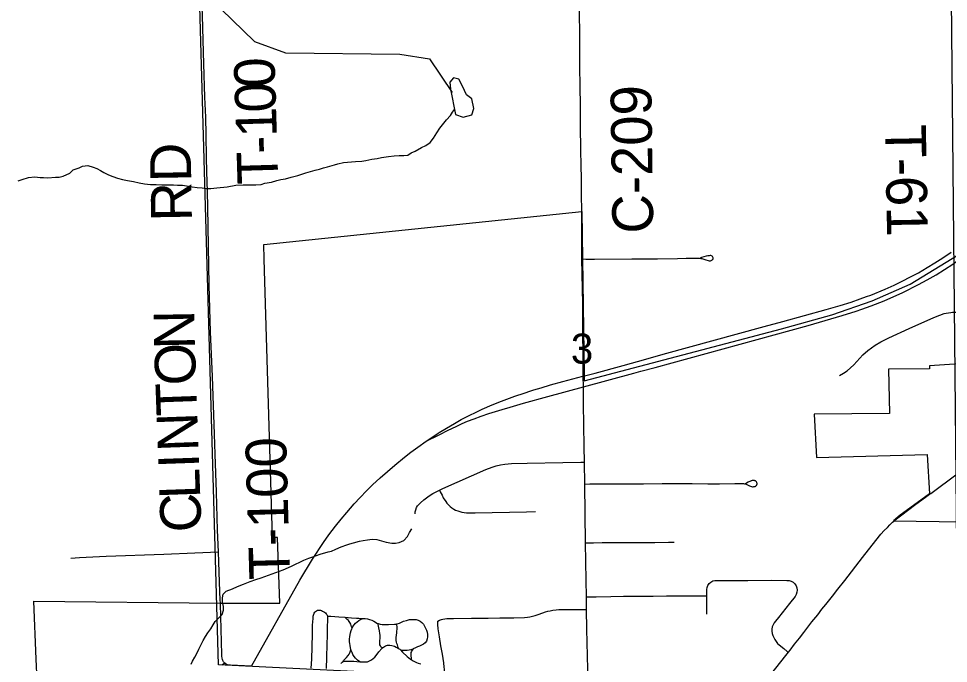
# Model space of a CAD drawing. Extents: x 0 to 34, y -5 to 22.
# Drawn here: x 2.826 to 4.121, y 15.62 to 16.518 of the extents above; entities that cross this region are included whole.
import ezdxf

# ---------------------------------------------------------------- set-up
doc = ezdxf.new("R2010")
doc.units = 0
for name, color, linetype in [('GM_X_City_Street', 7, 'Continuous'), ('GM_X_Corporation', 7, 'Continuous'), ('GM_X_County_Road', 7, 'Continuous'), ('GM_X_County_Road_Text', 7, 'Continuous'), ('GM_X_Minor_Lake', 7, 'Continuous'), ('GM_X_Minor_River', 7, 'Continuous'), ('GM_X_Rail_Line', 7, 'Continuous'), ('GM_X_Section', 7, 'Continuous'), ('GM_X_Section_Text', 7, 'Continuous'), ('GM_X_State_Route', 7, 'Continuous'), ('GM_X_Township_Road', 7, 'Continuous'), ('GM_X_Township_Road_Text', 7, 'Continuous')]:
    doc.layers.add(name, color=color, linetype=linetype)

msp = doc.modelspace()

# ---------------------------------------------------------------- linework, layer by layer
at = {"layer": 'GM_X_City_Street'}
for points in [[(3.9694, 16.021), (3.9748, 16.024), (3.98, 16.0275), (3.9848, 16.0315), (3.9892, 16.0358), (4.002, 16.0495), (4.0089, 16.0558), (4.0138, 16.0596), (4.0189, 16.0632), (4.027, 16.0678), (4.0382, 16.0733), (4.0666, 16.0862), (4.1006, 16.1016), (4.1092, 16.1052), (4.1151, 16.1072), (4.1181, 16.1079), (4.1243, 16.1088), (4.1266, 16.109), (4.1323, 16.1092), (4.1342, 16.1093)], [(3.3782, 15.8279), (3.3785, 15.8309), (3.3792, 15.8338), (3.3802, 15.8367), (3.3816, 15.8392), (3.3835, 15.8413), (3.3858, 15.8434), (3.3906, 15.8474), (3.398, 15.853), (3.4031, 15.8563), (3.4085, 15.8593), (3.4121, 15.861), (3.4169, 15.8633), (3.4767, 15.8899), (3.4854, 15.8932), (3.4913, 15.895), (3.4973, 15.8963), (3.5034, 15.8973), (3.5126, 15.898), (3.5344, 15.8985), (3.5842, 15.8995), (3.6092, 15.9002), (3.6144, 15.9003)], [(3.4121, 15.861), (3.4132, 15.8587), (3.4157, 15.8539), (3.4175, 15.8506), (3.4208, 15.8453), (3.4226, 15.8428), (3.4247, 15.8405), (3.427, 15.8384), (3.4294, 15.8364), (3.432, 15.8347), (3.4347, 15.8333), (3.4376, 15.8321), (3.4405, 15.8311), (3.4435, 15.8303), (3.4466, 15.8297), (3.4497, 15.8295), (3.4621, 15.8296), (3.5335, 15.8309), (3.5459, 15.8313)], [(3.6157, 15.7875), (3.6189, 15.7876), (3.6267, 15.7878), (3.6386, 15.7879), (3.6504, 15.7879), (3.6785, 15.7881), (3.7123, 15.7883), (3.7312, 15.7885), (3.739, 15.7885)], [(3.7846, 15.6881), (3.7847, 15.7006), (3.7846, 15.7139), (3.7846, 15.7224), (3.7849, 15.7255), (3.7859, 15.7284), (3.7876, 15.731), (3.79, 15.733), (3.7928, 15.7345), (3.7958, 15.7351), (3.8051, 15.7353), (3.8301, 15.7352), (3.8419, 15.7352), (3.8741, 15.7354), (3.896, 15.7353), (3.8991, 15.7351), (3.9021, 15.7341), (3.9048, 15.7326), (3.9071, 15.7305), (3.9088, 15.7279), (3.91, 15.725), (3.9103, 15.7219), (3.9101, 15.7187), (3.9091, 15.7157), (3.9075, 15.713), (3.8997, 15.7032), (3.8843, 15.6835), (3.8804, 15.6786), (3.8785, 15.6761), (3.8769, 15.6734), (3.8757, 15.6705), (3.8751, 15.6675), (3.8751, 15.6643), (3.8756, 15.6613), (3.8767, 15.6583), (3.8795, 15.6527), (3.8811, 15.65), (3.8829, 15.6475), (3.8852, 15.6453), (3.8918, 15.6404), (3.8966, 15.6364), (3.8982, 15.6351)], [(3.6168, 15.7124), (3.6207, 15.7124), (3.6305, 15.7125), (3.6509, 15.713), (3.6686, 15.7131), (3.6879, 15.7133), (3.7096, 15.7135), (3.7283, 15.7138), (3.7533, 15.7137), (3.775, 15.7139), (3.7823, 15.7139), (3.7846, 15.7139)], [(3.2334, 15.6128), (3.2342, 15.6256), (3.2352, 15.6604), (3.2355, 15.6728), (3.236, 15.6821), (3.2364, 15.6852), (3.2372, 15.6882), (3.2377, 15.6896), (3.2386, 15.6909), (3.2396, 15.6921), (3.2407, 15.693), (3.2422, 15.6937), (3.2435, 15.6939), (3.245, 15.6939), (3.2464, 15.6937), (3.2478, 15.6932), (3.2493, 15.6924), (3.252, 15.6909), (3.2533, 15.6899), (3.2544, 15.6889), (3.2553, 15.6879), (3.2559, 15.6866), (3.2561, 15.6853), (3.2564, 15.684), (3.2564, 15.6821), (3.256, 15.6796), (3.2558, 15.6709), (3.2557, 15.6586), (3.2554, 15.6462), (3.2548, 15.6277), (3.2543, 15.6125)], [(3.2561, 15.6853), (3.2609, 15.6855), (3.2721, 15.6847), (3.2805, 15.684), (3.2898, 15.6832), (3.2966, 15.6827), (3.2997, 15.6825), (3.3033, 15.6824), (3.3058, 15.6822), (3.3087, 15.6821), (3.3121, 15.6816), (3.3149, 15.681), (3.3179, 15.6799), (3.3205, 15.6786), (3.3231, 15.677), (3.3251, 15.6757), (3.3267, 15.6752), (3.3296, 15.6743), (3.3325, 15.6739), (3.335, 15.6739), (3.3413, 15.674), (3.3495, 15.6744), (3.3517, 15.6745), (3.3529, 15.6748), (3.3548, 15.6752), (3.3565, 15.6758), (3.3592, 15.6771), (3.3622, 15.6783), (3.3662, 15.6796), (3.3703, 15.6807), (3.3734, 15.681), (3.3765, 15.681), (3.3796, 15.6806), (3.3825, 15.6797), (3.3852, 15.6783), (3.3877, 15.6764), (3.3897, 15.6741), (3.3915, 15.6715), (3.3929, 15.6688), (3.3941, 15.6659), (3.3949, 15.6629), (3.3955, 15.6599), (3.3956, 15.6568), (3.3951, 15.6537), (3.394, 15.6508), (3.3921, 15.6484), (3.3897, 15.6465), (3.387, 15.6449), (3.3842, 15.6436), (3.3817, 15.6425), (3.3786, 15.6411), (3.3757, 15.6397), (3.3738, 15.6376), (3.373, 15.6364), (3.3724, 15.6348), (3.3721, 15.6333), (3.3721, 15.6318), (3.3722, 15.63), (3.3726, 15.6271), (3.3728, 15.6249)], [(3.4097, 15.6784), (3.4124, 15.6798), (3.4148, 15.6808), (3.4169, 15.6814), (3.4194, 15.6819), (3.4225, 15.6822), (3.4316, 15.6823), (3.4567, 15.6827), (3.4799, 15.6828), (3.4964, 15.683), (3.5159, 15.6833), (3.5307, 15.6836), (3.5346, 15.684), (3.5381, 15.6845), (3.5419, 15.6853), (3.5453, 15.6862), (3.5511, 15.6882), (3.5599, 15.6914), (3.5632, 15.6923), (3.5662, 15.693), (3.5701, 15.6937), (3.5746, 15.6943), (3.5783, 15.6945), (3.5937, 15.6948), (3.6061, 15.6948), (3.6145, 15.6948), (3.617, 15.6947)], [(3.2906, 15.6686), (3.2898, 15.6707), (3.2886, 15.6743), (3.2875, 15.6764), (3.2866, 15.6778), (3.2853, 15.6794), (3.2833, 15.6814), (3.2813, 15.6832), (3.2805, 15.684)], [(3.301, 15.622), (3.2978, 15.6243), (3.2966, 15.6253), (3.2951, 15.6268), (3.2933, 15.6292), (3.2917, 15.632), (3.2904, 15.6348), (3.2893, 15.6376), (3.2889, 15.639), (3.2883, 15.6411), (3.2877, 15.6445), (3.2872, 15.6475), (3.287, 15.6498), (3.287, 15.6536), (3.2873, 15.6568), (3.2877, 15.6598), (3.2883, 15.6624), (3.2893, 15.6655), (3.2903, 15.668), (3.2906, 15.6686), (3.2917, 15.6708), (3.2934, 15.6734), (3.2952, 15.6756), (3.2974, 15.6777), (3.2998, 15.6794), (3.3013, 15.6803), (3.3028, 15.6811), (3.3046, 15.6817), (3.3058, 15.6822)], [(3.3327, 15.6411), (3.3318, 15.6419), (3.3311, 15.6424), (3.3306, 15.643), (3.3298, 15.6441), (3.3293, 15.6454), (3.3292, 15.647), (3.3292, 15.65), (3.3296, 15.6559), (3.3295, 15.6589), (3.3292, 15.6613), (3.3286, 15.6648), (3.3275, 15.6691), (3.3271, 15.6715), (3.3269, 15.6739), (3.3267, 15.6752)], [(3.3553, 15.6403), (3.3548, 15.6419), (3.3535, 15.6453), (3.3528, 15.6473), (3.3522, 15.6494), (3.352, 15.6517), (3.3519, 15.6539), (3.352, 15.6558), (3.3526, 15.6622), (3.3529, 15.665), (3.353, 15.667), (3.353, 15.67), (3.3529, 15.6737), (3.3529, 15.6748)], [(3.4191, 15.6022), (3.4191, 15.6043), (3.4191, 15.6081), (3.419, 15.6103), (3.419, 15.6115), (3.4187, 15.6143), (3.4181, 15.6203), (3.4162, 15.6325), (3.4142, 15.6442), (3.4121, 15.6568), (3.4104, 15.6677), (3.4099, 15.6736), (3.4097, 15.6784)], [(3.275, 15.6195), (3.2756, 15.6205), (3.2765, 15.6214), (3.2778, 15.6223), (3.2796, 15.6225), (3.2815, 15.6226), (3.2848, 15.6226), (3.2927, 15.6225), (3.2972, 15.6223), (3.301, 15.622), (3.3045, 15.6219), (3.3072, 15.6218), (3.3098, 15.6218), (3.3117, 15.622), (3.3146, 15.6231), (3.3173, 15.6246), (3.3198, 15.6264), (3.3221, 15.6285), (3.324, 15.6308), (3.3278, 15.6357), (3.3319, 15.6404), (3.3327, 15.6411), (3.3342, 15.6424), (3.3369, 15.6439), (3.3398, 15.6448), (3.3429, 15.6451), (3.346, 15.6447), (3.3493, 15.6436), (3.352, 15.6424), (3.3539, 15.6414), (3.3553, 15.6403), (3.3568, 15.6393), (3.3578, 15.6383), (3.3608, 15.6353), (3.3671, 15.6294), (3.3717, 15.6257), (3.3728, 15.6249), (3.3756, 15.6231), (3.3783, 15.6217), (3.3802, 15.6208), (3.3827, 15.62), (3.386, 15.6192)], [(3.2778, 15.6223), (3.2786, 15.6235), (3.2797, 15.6248), (3.2827, 15.6278), (3.2851, 15.6305), (3.2864, 15.6324), (3.2874, 15.6344), (3.2882, 15.6369), (3.2889, 15.639)], [(3.3578, 15.6383), (3.3592, 15.6382), (3.3618, 15.638), (3.3643, 15.638), (3.367, 15.6381), (3.37, 15.6384), (3.3728, 15.6389), (3.3757, 15.6397)]]:
    msp.add_lwpolyline(points, dxfattribs=at)
at = {"layer": 'GM_X_Corporation'}
for points in [[(2.8518, 15.5958), (2.8506, 15.6253), (2.8471, 15.7063), (3.1069, 15.7037), (3.1897, 15.7036), (3.1867, 15.7952), (3.1797, 15.7951), (3.1679, 16.1829), (3.1674, 16.2037), (3.6104, 16.2495), (3.6116, 16.1837), (3.6137, 16.021), (3.6138, 16.0135), (3.8888, 16.0861), (3.9589, 16.1056), (4.0147, 16.125), (4.0677, 16.1481), (4.1346, 16.189)], [(4.1366, 16.0371), (4.0945, 16.0344), (4.0945, 16.0303), (4.0377, 16.0297), (4.0388, 15.968), (3.9339, 15.9668), (3.9371, 15.9064), (4.0913, 15.9107), (4.0946, 15.856), (4.054, 15.8261), (4.0447, 15.8182), (4.1399, 15.8168)], [(3.1147, 15.6191), (3.1131, 15.6201), (3.1088, 15.6173)]]:
    msp.add_lwpolyline(points, dxfattribs=at)
at = {"layer": 'GM_X_County_Road'}
for p, q in [((3.6106, 16.1833), (3.6106, 16.2489)), ((3.6126, 16.005), (3.6125, 16.02)), ((3.6145, 15.8695), (3.6144, 15.9003)), ((4.0956, 15.856), (4.0964, 15.8566)), ((3.6164, 15.7354), (3.6157, 15.7875)), ((3.6168, 15.7124), (3.6164, 15.7354)), ((3.617, 15.6947), (3.6168, 15.7124))]:
    msp.add_line(p, q, dxfattribs=at)
for points in [[(3.6106, 16.2489), (3.6102, 16.2742), (3.6099, 16.2866), (3.6098, 16.2985), (3.6097, 16.3108), (3.6092, 16.3377), (3.6088, 16.366), (3.6084, 16.3982), (3.6081, 16.4228), (3.6078, 16.4524), (3.6077, 16.4706), (3.6075, 16.498), (3.6073, 16.5248), (3.6072, 16.543)], [(3.6125, 16.02), (3.6125, 16.0421), (3.6119, 16.088), (3.6118, 16.1207), (3.6106, 16.1833)], [(3.6144, 15.9003), (3.6137, 15.9218), (3.613, 15.9816), (3.6126, 16.005)], [(4.0964, 15.8566), (4.1332, 15.884), (4.1401, 15.8892)], [(3.6157, 15.7875), (3.6151, 15.8279), (3.6145, 15.8695)], [(4.0456, 15.8183), (4.0487, 15.821), (4.0542, 15.8255), (4.0759, 15.8417), (4.0892, 15.8513), (4.0948, 15.8555), (4.0956, 15.856)], [(3.8982, 15.6351), (3.9005, 15.638), (3.9069, 15.6463), (3.9138, 15.6549), (3.9197, 15.6627), (3.9254, 15.6699), (3.931, 15.6773), (3.9391, 15.6875), (3.9448, 15.695), (3.9502, 15.7015), (3.9595, 15.7133), (3.9671, 15.7229), (3.9767, 15.7351), (4.0015, 15.767), (4.0201, 15.7911), (4.0271, 15.7995), (4.0317, 15.8048), (4.036, 15.8092), (4.0396, 15.8128), (4.0434, 15.8164), (4.0449, 15.8177), (4.0456, 15.8183)], [(3.6193, 15.5928), (3.6173, 15.6675), (3.617, 15.6947)], [(3.868, 15.5971), (3.8748, 15.6056), (3.8805, 15.6129), (3.8948, 15.6308), (3.8982, 15.6351)]]:
    msp.add_lwpolyline(points, dxfattribs=at)
at = {"layer": 'GM_X_Minor_Lake'}
for points in [[(3.4343, 16.3849), (3.4453, 16.3811), (3.4571, 16.3843), (3.46, 16.393), (3.4573, 16.4067), (3.45, 16.4123), (3.4442, 16.4244), (3.4392, 16.4339), (3.4316, 16.4357), (3.4267, 16.43), (3.4276, 16.4201)], [(3.4276, 16.4201), (3.4343, 16.3849)]]:
    msp.add_lwpolyline(points, dxfattribs=at)
at = {"layer": 'GM_X_Minor_River'}
for points in [[(3.0872, 16.2816), (3.0936, 16.2814), (3.102, 16.2827), (3.1164, 16.2841), (3.1286, 16.2862), (3.1385, 16.2868), (3.1442, 16.2865), (3.1563, 16.2868), (3.1636, 16.2873), (3.1689, 16.2889), (3.1784, 16.2906), (3.1855, 16.2927), (3.1912, 16.2943), (3.1977, 16.2952), (3.2056, 16.2972), (3.2147, 16.2997), (3.2204, 16.3013), (3.2261, 16.3033), (3.2325, 16.3054), (3.2389, 16.307), (3.245, 16.3086), (3.2507, 16.3103), (3.256, 16.3119), (3.2658, 16.3144), (3.2707, 16.316), (3.2783, 16.318), (3.295, 16.3191), (3.3038, 16.3197), (3.3095, 16.3205), (3.3178, 16.3226), (3.3254, 16.3235), (3.3315, 16.3248), (3.3413, 16.3261), (3.3489, 16.327), (3.3562, 16.3275), (3.3626, 16.3276), (3.3683, 16.3281), (3.3728, 16.3313), (3.3785, 16.3337), (3.3872, 16.3388), (3.3932, 16.3415), (3.3992, 16.3459), (3.404, 16.3517), (3.4085, 16.3593), (3.4125, 16.3655), (3.4162, 16.3705), (3.4218, 16.3771), (3.4274, 16.3833), (3.4304, 16.3879), (3.433, 16.3915)], [(2.8251, 16.2922), (2.8311, 16.2942), (2.8398, 16.2971), (2.8486, 16.2976), (2.8558, 16.297), (2.8604, 16.2967), (2.8665, 16.2964), (2.8771, 16.2974), (2.8825, 16.2975), (2.8881, 16.2988), (2.8972, 16.3031), (2.9021, 16.3078), (2.9104, 16.3102), (2.9149, 16.3126), (2.9225, 16.3135), (2.9298, 16.3114), (2.9351, 16.3092), (2.9401, 16.3066), (2.9448, 16.3037), (2.9513, 16.3007), (2.9571, 16.2982), (2.9636, 16.296), (2.9705, 16.2939), (2.9777, 16.2925), (2.9861, 16.2911), (2.9938, 16.2894), (3.0014, 16.288), (3.0098, 16.287), (3.0174, 16.2872), (3.0254, 16.2865), (3.0368, 16.2868), (3.0418, 16.2865), (3.0471, 16.2862), (3.054, 16.286), (3.0628, 16.2846), (3.0677, 16.2839), (3.0746, 16.2829), (3.0814, 16.2823), (3.0872, 16.2816)], [(3.0661, 15.6183), (3.0683, 15.6229), (3.0713, 15.6283), (3.0746, 15.6344), (3.0772, 15.6394), (3.0793, 15.644), (3.083, 15.6513), (3.0863, 15.6571), (3.0897, 15.6621), (3.0937, 15.6679), (3.097, 15.6733), (3.0996, 15.6779), (3.1052, 15.6834), (3.1097, 15.6876), (3.1115, 15.6938), (3.1114, 15.6991), (3.1098, 15.7051), (3.11, 15.7112), (3.1107, 15.7162), (3.1152, 15.7201), (3.1239, 15.7233), (3.131, 15.7269), (3.1393, 15.7301), (3.1484, 15.7337), (3.1563, 15.7365), (3.1639, 15.7389), (3.1945, 15.7498), (3.2062, 15.7553), (3.2232, 15.7633), (3.23, 15.7661), (3.2357, 15.7681), (3.2459, 15.7717), (3.2572, 15.7749), (3.2618, 15.7762), (3.2678, 15.779), (3.275, 15.7821), (3.2829, 15.785), (3.2875, 15.7862), (3.2924, 15.7878), (3.3007, 15.7902), (3.3057, 15.7907), (3.3121, 15.792), (3.3182, 15.7929), (3.3247, 15.7922), (3.3315, 15.7905), (3.338, 15.7887), (3.3457, 15.7873), (3.351, 15.7874), (3.3559, 15.7883), (3.3624, 15.7907), (3.3676, 15.7965), (3.3705, 15.8022), (3.3735, 15.8072)]]:
    msp.add_lwpolyline(points, dxfattribs=at)
at = {"layer": 'GM_X_Rail_Line'}
msp.add_lwpolyline([(3.1083, 16.5313), (3.1544, 16.4864), (3.1977, 16.4708), (3.357, 16.469), (3.3985, 16.4621), (3.4297, 16.4153)], dxfattribs=at)
at = {"layer": 'GM_X_Section'}
msp.add_lwpolyline([(4.1248, 16.5469), (4.1342, 15.5936), (3.6228, 15.592), (3.1044, 15.6177), (3.0783, 16.5351), (3.1825, 16.5361), (3.5929, 16.5408), (3.9967, 16.5453)], close=True, dxfattribs=at)
at = {"layer": 'GM_X_State_Route'}
msp.add_line((3.6126, 16.005), (3.683, 16.0242), dxfattribs=at)
for points in [[(3.6125, 16.02), (3.6288, 16.0243), (3.6679, 16.0349), (3.6997, 16.0438), (3.7238, 16.0506), (3.8644, 16.089), (3.8906, 16.0962), (3.9508, 16.1129), (3.9701, 16.1185), (3.9854, 16.1232), (3.9983, 16.1276), (4.007, 16.1308), (4.0131, 16.1331), (4.0332, 16.1413), (4.0456, 16.147), (4.055, 16.1514), (4.0701, 16.1592), (4.0793, 16.1642), (4.0915, 16.1713), (4.1022, 16.1779), (4.1132, 16.1849), (4.1251, 16.1927)], [(3.683, 16.0242), (3.6927, 16.0268), (3.7126, 16.0321), (3.9256, 16.0904), (3.9572, 16.0997), (3.973, 16.1043), (3.9927, 16.1107), (4.0005, 16.1133), (4.0136, 16.118), (4.0318, 16.1251), (4.0574, 16.1364), (4.0795, 16.1476), (4.0915, 16.1542), (4.1038, 16.1614), (4.1274, 16.1763), (4.1348, 16.1815)], [(3.5435, 16.0007), (3.554, 16.0039), (3.5668, 16.0077), (3.584, 16.0123), (3.6118, 16.0198), (3.6125, 16.02)], [(3.3938, 15.9293), (3.4116, 15.9382), (3.4243, 15.9446), (3.4356, 15.95), (3.444, 15.9539), (3.4513, 15.9571), (3.4605, 15.9607), (3.4701, 15.9641), (3.4811, 15.9678), (3.4996, 15.9736), (3.5108, 15.9768), (3.529, 15.9821), (3.5631, 15.9915), (3.6126, 16.005)], [(3.3938, 15.9293), (3.4031, 15.9356), (3.409, 15.9397), (3.4117, 15.9413), (3.4221, 15.9475), (3.4332, 15.9541), (3.4423, 15.9594), (3.4533, 15.9653), (3.4631, 15.97), (3.4714, 15.9739), (3.4854, 15.9799), (3.4987, 15.9852), (3.5172, 15.9919), (3.5299, 15.9964), (3.5396, 15.9996), (3.5435, 16.0007)], [(3.1503, 15.6156), (3.2177, 15.7357), (3.2353, 15.7649), (3.2508, 15.7881), (3.258, 15.7986), (3.2672, 15.8107), (3.2754, 15.8208), (3.2829, 15.83), (3.2932, 15.8419), (3.3015, 15.8507), (3.3106, 15.86), (3.3189, 15.8684), (3.3294, 15.8782), (3.3396, 15.8872), (3.3498, 15.8961), (3.3635, 15.907), (3.3721, 15.9138), (3.3818, 15.9208), (3.3938, 15.9293)]]:
    msp.add_lwpolyline(points, dxfattribs=at)
at = {"layer": 'GM_X_Township_Road'}
for points in [[(3.1042, 15.7751), (3.1029, 15.8055), (3.1014, 15.8584), (3.0997, 15.9112), (3.0987, 15.9391), (3.0958, 16.0196), (3.0932, 16.0816), (3.0915, 16.1469), (3.0896, 16.2555), (3.089, 16.2772), (3.0883, 16.3048), (3.0878, 16.3248), (3.0873, 16.3562), (3.0865, 16.381), (3.0854, 16.4089), (3.0839, 16.4553), (3.0826, 16.5049), (3.082, 16.5233), (3.0817, 16.534), (3.0817, 16.5373)], [(3.6106, 16.1833), (3.6161, 16.1831), (3.6282, 16.1831), (3.6803, 16.1833), (3.7157, 16.1837), (3.7436, 16.184), (3.756, 16.1846), (3.7684, 16.1846), (3.7745, 16.1844), (3.776, 16.1842), (3.7775, 16.1839), (3.7805, 16.183), (3.7834, 16.182), (3.7864, 16.1811), (3.788, 16.1808), (3.7895, 16.1808), (3.7907, 16.1812), (3.7917, 16.1816), (3.7922, 16.182), (3.7927, 16.1825), (3.7934, 16.1839), (3.7934, 16.1847), (3.7929, 16.1859), (3.7925, 16.1866), (3.792, 16.1871), (3.791, 16.1877), (3.79, 16.188), (3.789, 16.188), (3.788, 16.1879), (3.7859, 16.1876), (3.7836, 16.187), (3.7773, 16.1852), (3.7753, 16.1846)], [(3.6145, 15.8695), (3.6215, 15.87), (3.6494, 15.8699), (3.6742, 15.8699), (3.6964, 15.87), (3.7222, 15.8702), (3.7426, 15.8702), (3.7642, 15.8704), (3.786, 15.8701), (3.802, 15.87), (3.8235, 15.8703), (3.8325, 15.8704), (3.8358, 15.8703), (3.8369, 15.8701), (3.8378, 15.8699), (3.8394, 15.8692), (3.8439, 15.8672), (3.847, 15.866), (3.8481, 15.8658), (3.8492, 15.8659), (3.8502, 15.866), (3.851, 15.8661), (3.8519, 15.8664), (3.8527, 15.8668), (3.8535, 15.8674), (3.854, 15.868), (3.8543, 15.8688), (3.8545, 15.8696), (3.8545, 15.8703), (3.8544, 15.8711), (3.8541, 15.8719), (3.8538, 15.8725), (3.8534, 15.8731), (3.8528, 15.8735), (3.8523, 15.8739), (3.8516, 15.8742), (3.8508, 15.8744), (3.8499, 15.8745), (3.8484, 15.8745), (3.8477, 15.8744), (3.8469, 15.8742), (3.8462, 15.8739), (3.8453, 15.8736), (3.8422, 15.8721), (3.8397, 15.8709), (3.8381, 15.87)], [(2.8986, 15.7665), (2.9109, 15.7674), (2.948, 15.769), (3.0283, 15.7719), (3.0716, 15.7735), (3.1042, 15.7751)], [(3.1069, 15.7076), (3.1059, 15.7326), (3.1048, 15.761), (3.1042, 15.7751)], [(3.107, 15.7028), (3.107, 15.7038), (3.1069, 15.7076)], [(3.1133, 15.6196), (3.1125, 15.6203), (3.1117, 15.6213), (3.1112, 15.6219), (3.1108, 15.6226), (3.1104, 15.6236), (3.1099, 15.6252), (3.1096, 15.6268), (3.1092, 15.6296), (3.109, 15.6322), (3.107, 15.7028)], [(3.1503, 15.6156), (3.121, 15.6172), (3.119, 15.6173), (3.1167, 15.6178), (3.1149, 15.6185), (3.1133, 15.6196)]]:
    msp.add_lwpolyline(points, dxfattribs=at)

# ---------------------------------------------------------------- texts
at = {"layer": 'GM_X_County_Road_Text'}
msp.add_text('C-209', height=0.05682, rotation=90.8208, dxfattribs=at).set_placement((3.7101, 16.2191))
at = {"layer": 'GM_X_Section_Text'}
msp.add_text('3', height=0.0419, rotation=0, dxfattribs=at).set_placement((3.5952, 16.0374))
at = {"layer": 'GM_X_Township_Road_Text'}
for s, height, rotation, p in [('0', 0.0568, 91.7682, (3.1836, 16.423)), ('0', 0.0568, 91.7639, (3.1847, 16.3883)), ('1', 0.0568, 91.7566, (3.1858, 16.3536)), ('T-61', 0.05682, 271.061, (4.0328, 16.3703)), ('-', 0.0568, 91.7521, (3.1865, 16.3305)), ('RD', 0.05682, 90.9673, (3.0674, 16.2361)), ('T', 0.0568, 91.7365, (3.1877, 16.2881)), ('N', 0.0568, 91.0164, (3.0716, 16.0578)), ('O', 0.0568, 92.0039, (3.0734, 16.0081)), ('T', 0.0568, 92.066, (3.0749, 15.9657)), ('N', 0.0568, 92.0623, (3.0767, 15.9157)), ('T-100', 0.05682, 91.6698, (3.2042, 15.7373)), ('I', 0.0568, 92.0678, (3.0776, 15.8924)), ('L', 0.0568, 92.0618, (3.0791, 15.8499)), ('C', 0.0568, 92.0651, (3.0808, 15.8033))]:
    msp.add_text(s, height=height, rotation=rotation, dxfattribs=at).set_placement(p)

doc.saveas('drawing.dxf')
